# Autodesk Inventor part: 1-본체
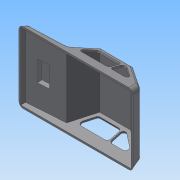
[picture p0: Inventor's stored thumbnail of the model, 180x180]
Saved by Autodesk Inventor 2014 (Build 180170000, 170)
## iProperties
Created: 2015-05
Part Number: 1-본체
Material: Generic
Document SubType Name: Modeling
Designer: Administrator
Density: 1 g/cm^3
Appearance: Default
Author: Administrator
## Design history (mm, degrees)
sketch "스케치1"
  geometry: L1 (-61, 0)-(61, 0); L2 (-61, 0)-(-59.392, 6); L3 (-59.392, 6)-(-17.392, 8.201); L4 (-17.392, 8.201)-(-3.771, 30); L5 (-3.771, 30)-(31, 30); L6 (31, 30)-(58.321, 10); L7 (58.321, 10)-(61, 0); 3 further points
  constraints: 14 end point, 1 coincident, 1 horizontal, 1 midpoint, 1 parallel
  dimensions: "d0" = 122 distance of L1.start L1.end; "d1" = 6 vertical distance of L1.start L2.end; "d2" = 105 deg angle of L1 L2; "d3" = 42 horizontal distance of L2.end L3.end; "d4" = 3 deg angle of L1 L3; "d5" = 30 horizontal distance of L1.end L5.end; "d6" = 125 deg angle of L4 L3; "d7" = 20 vertical distance of L6.end L5.end; "d8" = 105 deg angle of L1 L7; "d9" = 30 distance between parallel lines of L1 L5; "d10" = 58.92148 distance from line of point (0, 0) L7; "d11" = 42.51835 distance from line of point (0, 0) L6
extrude "돌출1" new body sketch "스케치1" stored distance "d12" = 76; taper "d13" = 0 deg
node "작업 평면1"
sketch "스케치2"
  geometry: L1 (0, 38)-(0, -38) reference; L2 (8.201, -38)-(30, -38) reference; L3 (6, -38)-(8.201, -38) reference; L4 (0, -38)-(6, -38) reference; L5 (30, 38)-(8.201, 38) reference; L6 (8.201, 38)-(6, 38) reference; L7 (6, 38)-(0, 38) reference; L8 (30, -38)-(30, 38) reference; L9 (0, -38)-(30, -29.962); L10 (0, 38)-(30, 29.962); L11 (30, 29.962)-(30, 38); L12 (30, -29.962)-(30, -38); 1 further point
  constraints: 8 end point, 2 collinear, 2 point on line
  dimensions: "d15" = 105 deg angle of L1 L9; "d16" = 105 deg angle of L1 L10
extrude "돌출2" cut sketch "스케치2" stored distance "d17" = 76; taper "d18" = 0 deg
feature "쉘1" dims "d19" = 2
node "작업 평면2"
sketch "스케치4"
  geometry: L1 (59.392, 6)-(17.392, 8.201) reference; L2 (50, 6.492)-(48.142, 11.596); L3 (48.142, 11.596)-(32.079, 12.438); L4 (32.079, 12.438)-(30, 7.54); L5 (50, 6.492)-(52.432, -0.19); L6 (30, 7.54)-(27.536, 1.735); L7 (61, 0)-(59.392, 6) reference; L8 (61, 0)-(61, 15.359); L9 (61, 15.359)-(52.326, 15.359); 1 further point
  constraints: 14 end point, 2 collinear, 2 point on line, 1 parallel, 1 perpendicular, 1 vertical
  dimensions: "d22" = 11 distance from line of L8 L2.start; "d23" = 70 deg angle of L2 L9; "d24" = 70 deg angle of L4 L1; "d25" = 20 horizontal distance of L4.end L2.start; "d27" = 5 distance between parallel lines of L1 L3
extrude "돌출3" join sketch "스케치4" stored distance "d28" = 26; taper "d29" = 0 deg
sketch "스케치5"
  geometry: L1 (43.608, 8.49)-(57.229, 31.058) reference; L2 (92, 31.058)-(119.321, 10.353) reference; L3 (57.229, 31.058)-(92, 31.058) reference; L4 (43.608, 8.49)-(51.325, 8.49); L5 (59.176, 24.609)-(53.744, 15.609); L6 (56.313, 11.058)-(81.998, 11.058); L7 (84.998, 14.058)-(84.998, 23.058); L8 (81.998, 26.058)-(61.745, 26.058); L9 (86.311, 23.058)-(86.311, 14.058); L10 (89.311, 11.058)-(101.186, 11.058); L11 (102.998, 16.449)-(91.123, 25.449); L12 (0, 0)-(122, 0) reference; L13 (89.311, 26.058)-(97.253, 26.058); A1 r 3 centre (61.745, 23.058) between (61.745, 26.058) and (59.176, 24.609); A2 r 3 centre (56.313, 14.058) between (53.744, 15.609) and (56.313, 11.058); A3 r 3 centre (81.998, 14.058) between (81.998, 11.058) and (84.998, 14.058); A4 r 3 centre (81.998, 23.058) between (84.998, 23.058) and (81.998, 26.058); A5 r 3 centre (89.311, 23.058) between (91.123, 25.449) and (86.311, 23.058); A6 r 3 centre (89.311, 14.058) between (86.311, 14.058) and (89.311, 11.058); A7 r 3 centre (101.186, 14.058) between (101.186, 11.058) and (102.998, 16.449); 6 further points
  constraints: 18 end point, 15 point on circle, 15 tangent, 10 point on line, 7 centre point, 5 equal radius, 5 parallel, 4 perpendicular, 1 collinear
  dimensions: "d30" = 5 distance between parallel lines of L1 L5; "d31" = 5 distance between parallel lines of L8 L3; "d32" = 34 distance of point (50.998, 11.058) point (84.998, 11.058); "d33" = 5 distance between parallel lines of L11 L2; "d34" = 15 vertical distance of point (60.051, 26.058) point (50.998, 11.058); "d36" = 3 radius of A1; "d50" = 3 radius of A5; "d51" = 15 distance between parallel lines of L10 L13
extrude "돌출4" cut sketch "스케치5" distance "d37" = 2; taper "d38" = 0 deg
node "작업 평면3"
node "작업 평면5"
sketch "스케치8"
  geometry: L1 (-16.085, 26)-(0, 26) reference; L2 (-16.085, 26)-(-16.085, 0) reference; L3 (0, 26)-(0, 0) reference; L4 (0, 0)-(-16.085, 0) reference; L5 (-2, 24)-(-14.085, 24); L6 (-14.085, 24)-(-14.085, 2); L7 (-14.085, 2)-(-2, 2); L8 (-2, 2)-(-2, 24); 1 further point
  constraints: 8 end point, 3 other
  dimensions: "d44" = 2 distance between parallel lines of L5 L1
extrude "돌출5" cut sketch "스케치8" stored distance "d45" = 2; taper "d46" = 0 deg
fillet "모깎기3" dims "d47" = 3
fillet "모깎기4" dims "d48" = 3
fillet "모깎기5" dims "d49" = 3
fillet "모깎기6" dims "d52" = 3
fillet "모깎기7" dims "d53" = 5
node "솔리드1"
mirror "대칭1"
other parameters: "d21" = 0, "d39" = 0, "d43" = -2
